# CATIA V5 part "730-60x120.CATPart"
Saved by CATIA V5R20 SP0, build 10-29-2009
Part number: 730-60x120
Definition: NONE
Nomenclature: 730-60x120
Source: Unknown
Description: 730-60x120
Bounding box of the stored display mesh (mm): x -34 to 34, y -33.316 to 33.316, z 0 to 120
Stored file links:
  C:\Users\Utente\Desktop\IO LAVORO\3D X SITO CF\X SITO\730\730-60x120.CATPart
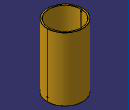
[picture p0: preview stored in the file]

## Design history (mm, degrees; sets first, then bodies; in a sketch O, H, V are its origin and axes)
Body1 "730-60x120" (main body)
  Solid1: solid without history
